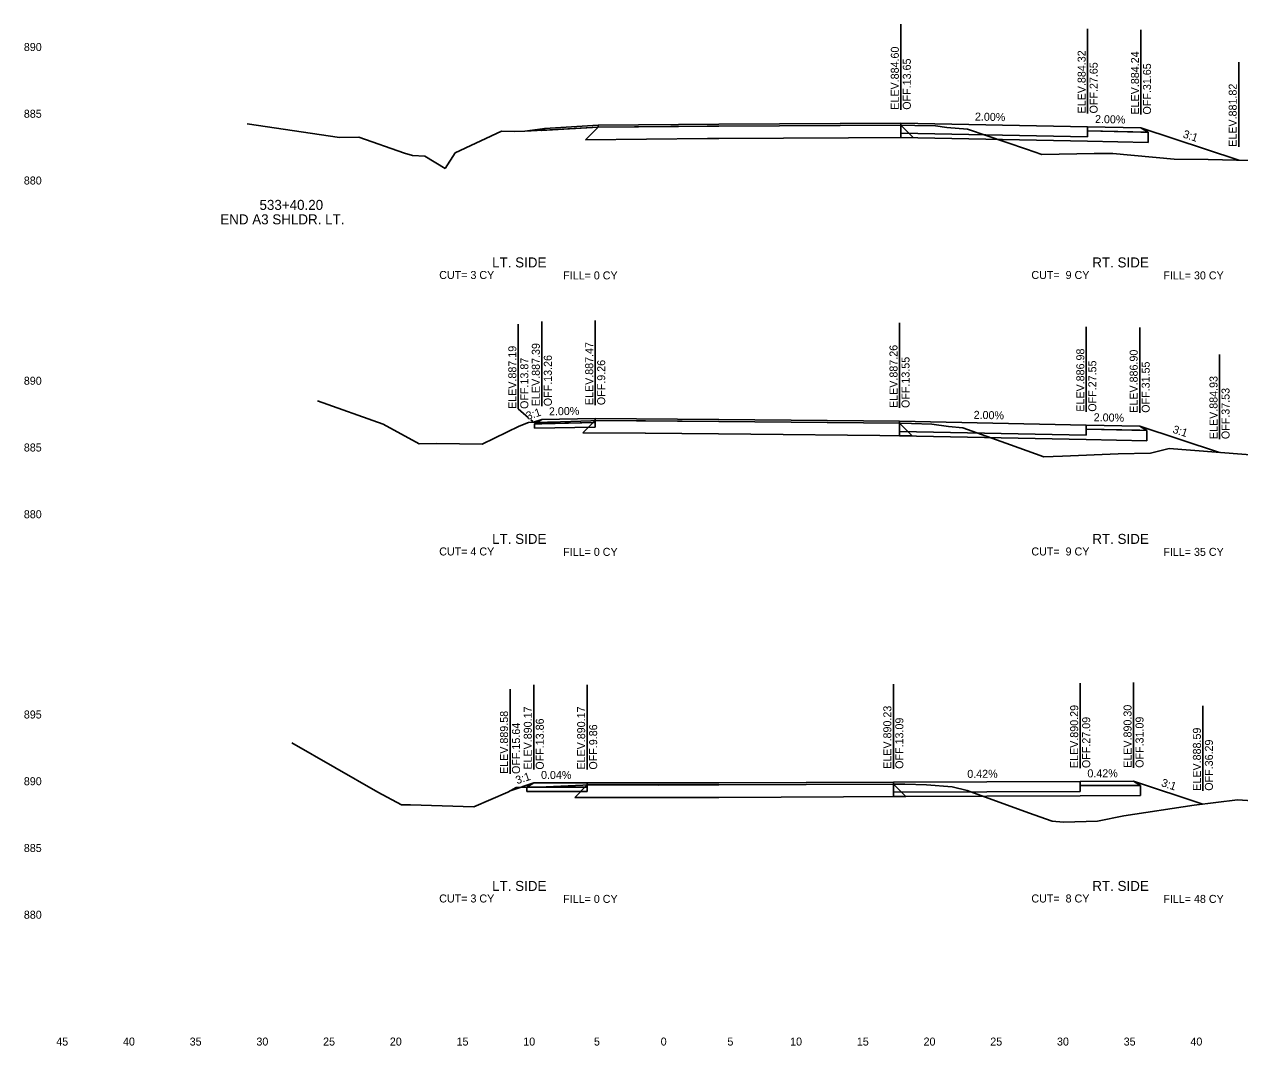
# Model space of a CAD drawing. Extents: x -4 to 359, y 0 to 1436.
# Drawn here: x -3.9 to 87.2, y 600.5 to 677 of the extents above; entities that cross this region are included whole.
import ezdxf

# ---------------------------------------------------------------- set-up
doc = ezdxf.new("R2010")
doc.units = 0
for name, color, linetype in [('XS-Existing subsurface-pavement', 7, 'Continuous'), ('XS-Existing surface-ground', 7, 'Continuous'), ('XS-Proposed Finish Grade', 7, 'Continuous'), ('XS-Proposed subsurface-aggregate layer 1', 7, 'Continuous'), ('XS-Proposed surface-ground', 7, 'Continuous'), ('XS-Proposed surface-pavement', 7, 'Continuous'), ('XS-Proposed surface-shoulder', 7, 'Continuous'), ('XS-Text-ditch slope', 7, 'Continuous'), ('XS-Text-earthwork labels', 7, 'Continuous'), ('XS-Text-elevation', 7, 'Continuous'), ('XS-Text-offset label', 7, 'Continuous'), ('XS-Text-pavement elevation', 7, 'Continuous'), ('XS-Text-pavement slope', 7, 'Continuous'), ('XS-Text-profile report', 7, 'Continuous'), ('XS-Text-shoulder elevation', 7, 'Continuous'), ('XS-Text-shoulder slope', 7, 'Continuous'), ('XS-Text-tie elevation', 7, 'Continuous'), ('XS-Text-tie offset', 7, 'Continuous')]:
    doc.layers.add(name, color=color, linetype=linetype)

msp = doc.modelspace()

# ---------------------------------------------------------------- linework, layer by layer
at = {"layer": 'XS-Existing subsurface-pavement'}
for p, q in [((39.087, 669.279), (38.14, 668.333)), ((61.778, 669.438), (62.711, 668.506)), ((38.14, 668.333), (47.284, 668.421)), ((47.28, 668.421), (48.135, 668.426)), ((48.135, 668.426), (62.711, 668.506)), ((38.873, 647.302), (37.948, 646.377)), ((61.68, 647.097), (62.627, 646.15)), ((37.948, 646.377), (42.631, 646.353)), ((42.626, 646.353), (48.121, 646.297)), ((48.121, 646.297), (62.627, 646.15)), ((38.27, 620.007), (37.335, 619.072)), ((61.217, 620.065), (62.151, 619.132)), ((37.335, 619.072), (43.636, 619.055)), ((43.642, 619.055), (48.134, 619.073)), ((48.134, 619.073), (62.151, 619.132))]:
    msp.add_line(p, q, dxfattribs=at)
at = {"layer": 'XS-Existing surface-ground'}
for p, q in [((12.8, 669.521), (19.7, 668.51)), ((28.377, 667.355), (31.846, 668.982)), ((31.846, 668.982), (32.804, 668.962)), ((32.804, 668.962), (33.597, 668.977)), ((33.597, 668.977), (35.475, 669.075)), ((35.475, 669.075), (39.087, 669.279)), ((39.087, 669.279), (47.275, 669.359)), ((47.275, 669.359), (48.13, 669.363)), ((48.13, 669.363), (61.778, 669.438)), ((61.778, 669.438), (62.819, 669.412)), ((62.819, 669.412), (64.373, 669.383)), ((64.373, 669.383), (65.217, 669.254)), ((65.217, 669.254), (66.774, 669.134)), ((66.774, 669.134), (71.194, 667.624)), ((19.7, 668.51), (21.147, 668.532)), ((21.147, 668.532), (24.578, 667.342)), ((24.578, 667.342), (25.175, 667.153)), ((25.175, 667.153), (26.095, 667.115)), ((26.095, 667.115), (27.635, 666.177)), ((27.635, 666.177), (28.377, 667.355)), ((71.194, 667.624), (72.349, 667.219)), ((72.349, 667.219), (76.263, 667.297)), ((76.263, 667.297), (77.679, 667.317)), ((77.679, 667.317), (82.253, 666.889)), ((82.253, 666.889), (84.816, 666.868)), ((84.816, 666.868), (88.02, 666.783)), ((18.065, 648.788), (22.992, 647.042)), ((22.992, 647.042), (25.681, 645.548)), ((30.394, 645.541), (33.187, 646.872)), ((33.187, 646.872), (33.886, 647.167)), ((33.886, 647.167), (35.303, 647.187)), ((35.303, 647.187), (35.512, 647.182)), ((35.512, 647.182), (38.539, 647.29)), ((38.539, 647.29), (38.873, 647.309)), ((38.873, 647.309), (42.636, 647.29)), ((42.636, 647.29), (48.13, 647.235)), ((48.13, 647.235), (61.68, 647.097)), ((61.68, 647.097), (62.589, 647.073)), ((62.589, 647.073), (64.108, 647.036)), ((64.108, 647.036), (65.347, 646.845)), ((65.347, 646.845), (66.422, 646.759)), ((66.422, 646.759), (69.996, 645.492)), ((25.681, 645.548), (26.999, 645.576)), ((26.999, 645.576), (30.394, 645.541)), ((69.996, 645.492), (72.5, 644.585)), ((80.498, 644.868), (81.884, 645.206)), ((81.884, 645.206), (100.006, 643.781)), ((72.5, 644.585), (73.897, 644.625)), ((73.897, 644.625), (78.072, 644.801)), ((78.072, 644.801), (80.498, 644.868)), ((16.137, 623.15), (22.581, 619.452)), ((22.581, 619.452), (24.357, 618.507)), ((29.783, 618.354), (32.329, 619.471)), ((32.329, 619.471), (32.944, 619.825)), ((32.944, 619.825), (34.502, 619.831)), ((34.502, 619.831), (34.66, 619.833)), ((34.66, 619.833), (37.951, 619.995)), ((37.951, 619.995), (38.27, 620.007)), ((38.27, 620.007), (43.638, 619.992)), ((43.638, 619.992), (48.13, 620.011)), ((48.13, 620.011), (61.217, 620.065)), ((61.217, 620.065), (62.086, 620.057)), ((62.086, 620.057), (63.713, 620.014)), ((63.713, 620.014), (65.633, 619.859)), ((65.633, 619.859), (66.749, 619.591)), ((66.749, 619.591), (71.354, 617.924)), ((24.357, 618.507), (25.038, 618.527)), ((25.038, 618.527), (29.783, 618.354)), ((83.759, 618.486), (87.015, 618.901)), ((87.015, 618.901), (89.541, 618.729)), ((71.354, 617.924), (73.109, 617.302)), ((76.519, 617.295), (78.502, 617.68)), ((78.502, 617.68), (83.759, 618.486)), ((73.109, 617.302), (73.977, 617.221)), ((73.977, 617.221), (76.519, 617.295))]:
    msp.add_line(p, q, dxfattribs=at)
at = {"layer": 'XS-Proposed Finish Grade'}
for points in [[(39.087, 669.425), (48.13, 669.509), (61.778, 669.584)], [(61.778, 669.584), (75.778, 669.304)], [(75.778, 669.304), (79.778, 669.224)], [(38.873, 647.455), (34.873, 647.375)], [(38.873, 647.455), (48.13, 647.38), (61.68, 647.243)], [(61.68, 647.243), (75.68, 646.963)], [(75.68, 646.963), (79.68, 646.883)], [(38.27, 620.153), (34.27, 620.151)], [(38.27, 620.153), (48.13, 620.157), (61.217, 620.211)], [(61.217, 620.211), (75.219, 620.269)], [(75.219, 620.269), (79.219, 620.286)]]:
    msp.add_lwpolyline(points, dxfattribs=at)
at = {"layer": 'XS-Proposed subsurface-aggregate layer 1'}
for points in [[(61.778, 668.834), (75.778, 668.554)], [(61.778, 668.501), (61.778, 668.834)], [(75.778, 668.554), (75.778, 668.991)], [(75.778, 668.991), (80.317, 668.901)], [(80.317, 668.901), (80.317, 668.13)], [(80.317, 668.13), (75.778, 668.221), (61.778, 668.501)], [(38.873, 647.143), (34.334, 647.052)], [(34.334, 647.052), (34.334, 646.719)], [(34.334, 646.719), (38.873, 646.809)], [(38.873, 646.809), (38.873, 647.143)], [(61.68, 646.493), (75.68, 646.213)], [(61.68, 646.16), (61.68, 646.493)], [(80.219, 645.789), (75.68, 645.88), (61.68, 646.16)], [(75.68, 646.213), (75.68, 646.651)], [(75.68, 646.651), (80.219, 646.56)], [(80.219, 646.56), (80.219, 645.789)], [(38.27, 619.84), (33.749, 619.838)], [(33.749, 619.838), (33.749, 619.505)], [(33.749, 619.505), (38.27, 619.507)], [(38.27, 619.507), (38.27, 619.84)], [(61.217, 619.461), (75.219, 619.519)], [(61.217, 619.128), (61.217, 619.461)], [(75.219, 619.957), (79.736, 619.975)], [(75.219, 619.519), (75.219, 619.957)], [(79.736, 619.975), (79.736, 619.205)], [(79.736, 619.205), (75.219, 619.186), (61.217, 619.128)]]:
    msp.add_lwpolyline(points, dxfattribs=at)
at = {"layer": 'XS-Proposed surface-ground'}
for points in [[(35.087, 669.179), (33.597, 668.977)], [(79.778, 669.224), (87.102, 666.807)], [(34.873, 647.375), (34.258, 647.172)], [(79.68, 646.883), (85.663, 644.909)], [(34.27, 620.151), (32.488, 619.563)], [(79.219, 620.286), (84.418, 618.57)]]:
    msp.add_lwpolyline(points, dxfattribs=at)
at = {"layer": 'XS-Proposed surface-pavement'}
for points in [[(61.778, 669.584), (48.13, 669.509), (39.087, 669.425)], [(61.778, 669.584), (75.778, 669.304)], [(61.778, 668.834), (61.778, 669.584)], [(61.778, 669.438), (61.778, 669.584)], [(39.087, 669.279), (48.13, 669.363), (61.778, 669.438)], [(39.087, 669.425), (39.087, 669.279)], [(75.778, 668.554), (61.778, 668.834)], [(75.778, 669.304), (75.778, 668.554)], [(38.873, 647.455), (38.873, 647.309)], [(61.68, 647.243), (48.13, 647.38), (38.873, 647.455)], [(38.873, 647.309), (48.13, 647.235), (61.68, 647.097)], [(61.68, 647.243), (75.68, 646.963)], [(61.68, 646.493), (61.68, 647.243)], [(61.68, 647.097), (61.68, 647.243)], [(75.68, 646.963), (75.68, 646.213)], [(75.68, 646.213), (61.68, 646.493)], [(61.217, 620.211), (48.13, 620.157), (38.27, 620.153)], [(38.27, 620.153), (38.27, 620.007)], [(38.27, 620.007), (48.13, 620.011), (61.217, 620.065)], [(61.217, 620.211), (75.219, 620.269)], [(61.217, 619.461), (61.217, 620.211)], [(61.217, 620.065), (61.217, 620.211)], [(75.219, 619.519), (61.217, 619.461)], [(75.219, 620.269), (75.219, 619.519)]]:
    msp.add_lwpolyline(points, dxfattribs=at)
at = {"layer": 'XS-Proposed surface-shoulder'}
for p, q in [((39.096, 669.28), (34.816, 669.016)), ((35.087, 669.179), (34.816, 669.016)), ((39.087, 669.425), (35.087, 669.179))]:
    msp.add_line(p, q, dxfattribs=at)
for points in [[(75.778, 669.304), (79.778, 669.224), (80.317, 668.901)], [(75.778, 668.991), (75.778, 669.304)], [(80.317, 668.901), (79.778, 668.911), (75.778, 668.991)], [(38.873, 647.455), (34.873, 647.375), (34.334, 647.052)], [(34.334, 647.052), (34.873, 647.063), (38.873, 647.143)], [(38.873, 647.143), (38.873, 647.455)], [(75.68, 646.963), (79.68, 646.883), (80.219, 646.56)], [(75.68, 646.651), (75.68, 646.963)], [(80.219, 646.56), (79.68, 646.571), (75.68, 646.651)], [(38.27, 620.153), (34.27, 620.151), (33.749, 619.838)], [(33.749, 619.838), (34.27, 619.838), (38.27, 619.84)], [(38.27, 619.84), (38.27, 620.153)], [(75.219, 620.269), (79.219, 620.286), (79.736, 619.975)], [(75.219, 619.957), (75.219, 620.269)], [(79.736, 619.975), (79.219, 619.973), (75.219, 619.957)]]:
    msp.add_lwpolyline(points, dxfattribs=at)
at = {"layer": 'XS-Text-tie offset'}
for p, q in [((61.778, 670.584), (61.778, 676.982)), ((75.778, 670.304), (75.778, 676.654)), ((79.778, 670.224), (79.778, 676.574)), ((87.102, 667.807), (87.102, 674.157)), ((33.11, 648.172), (33.11, 654.522)), ((34.873, 648.375), (34.873, 654.725)), ((38.873, 648.455), (38.873, 654.805)), ((61.68, 648.243), (61.68, 654.621)), ((75.68, 647.963), (75.68, 654.313)), ((79.68, 647.883), (79.68, 654.281)), ((85.663, 645.909), (85.663, 652.259)), ((33.11, 648.172), (33.886, 647.496)), ((34.054, 647.35), (34.193, 647.229)), ((75.219, 621.269), (75.219, 627.619)), ((79.219, 621.286), (79.219, 627.684)), ((32.488, 620.827), (32.488, 627.177)), ((34.27, 621.151), (34.27, 627.501)), ((38.27, 621.153), (38.27, 627.503)), ((61.217, 621.211), (61.217, 627.561)), ((84.418, 619.57), (84.418, 625.92))]:
    msp.add_line(p, q, dxfattribs=at)

# ---------------------------------------------------------------- texts
at = {"layer": 'XS-Text-ditch slope'}
for rotation, p in [(341.73711, (82.87, 668.52)), (18.26289, (33.806, 647.339)), (341.73711, (82.101, 646.4)), (18.26289, (33.02, 620.054)), (341.73711, (81.248, 619.932))]:
    msp.add_text('3:1', height=0.6, rotation=rotation, dxfattribs=at).set_placement(p)
at = {"layer": 'XS-Text-earthwork labels'}
for s, height, p in [('533+40.20', 0.75, (13.713, 663.08)), ('END A3 SHLDR. LT.', 0.75, (10.774, 661.998)), ('LT. SIDE', 0.75, (31.148, 658.771)), ('RT. SIDE', 0.75, (76.127, 658.771)), (' CUT= 3 CY           ', 0.6, (26.96, 657.906)), ('FILL= 0 CY           ', 0.6, (36.472, 657.874)), (' CUT=  9 CY           ', 0.6, (71.341, 657.906)), ('FILL= 30 CY           ', 0.6, (81.452, 657.874)), ('LT. SIDE', 0.75, (31.148, 638.06)), ('RT. SIDE', 0.75, (76.127, 638.06)), (' CUT= 4 CY           ', 0.6, (26.96, 637.195)), ('FILL= 0 CY           ', 0.6, (36.472, 637.163)), (' CUT=  9 CY           ', 0.6, (71.341, 637.195)), ('FILL= 35 CY           ', 0.6, (81.452, 637.163)), ('LT. SIDE', 0.75, (31.148, 612.065)), ('RT. SIDE', 0.75, (76.127, 612.065)), (' CUT= 3 CY           ', 0.6, (26.96, 611.2)), ('FILL= 0 CY           ', 0.6, (36.472, 611.168)), (' CUT=  8 CY           ', 0.6, (71.341, 611.2)), ('FILL= 48 CY           ', 0.6, (81.452, 611.168))]:
    msp.add_text(s, height=height, dxfattribs=at).set_placement(p)
at = {"layer": 'XS-Text-elevation'}
for s, p in [('           890           ', (-6.4, 674.982)), ('           885           ', (-6.4, 669.982)), ('           880           ', (-6.4, 664.982)), ('           890           ', (-6.4, 649.982)), ('           885           ', (-6.4, 644.982)), ('           880           ', (-6.4, 639.982)), ('           895           ', (-6.4, 624.982)), ('           890           ', (-6.4, 619.982)), ('           885           ', (-6.4, 614.982)), ('           880           ', (-6.4, 609.982))]:
    msp.add_text(s, height=0.6, dxfattribs=at).set_placement(p)
at = {"layer": 'XS-Text-offset label'}
for s, p in [('           45           ', (-3.97, 600.482)), ('           40           ', (1.03, 600.482)), ('           35           ', (6.03, 600.482)), ('           30           ', (11.03, 600.482)), ('           25           ', (16.03, 600.482)), ('           20           ', (21.03, 600.482)), ('           15           ', (26.03, 600.482)), ('           10           ', (31.03, 600.482)), ('           5           ', (36.33, 600.482)), ('           0           ', (41.33, 600.482)), ('           0           ', (41.33, 600.482)), ('           5           ', (46.33, 600.482)), ('           10           ', (51.03, 600.482)), ('           15           ', (56.03, 600.482)), ('           20           ', (61.03, 600.482)), ('           25           ', (66.03, 600.482)), ('           30           ', (71.03, 600.482)), ('           35           ', (76.03, 600.482)), ('           40           ', (81.03, 600.482))]:
    msp.add_text(s, height=0.6, dxfattribs=at).set_placement(p)
at = {"layer": 'XS-Text-pavement elevation'}
for s, p in [('ELEV.884.60', (61.628, 670.584)), ('ELEV.884.32', (75.628, 670.304)), ('OFF.13.65', (62.528, 670.584)), ('OFF.27.65', (76.528, 670.304)), ('ELEV.887.47', (38.723, 648.455)), ('ELEV.887.39', (34.723, 648.375)), ('ELEV.887.26', (61.53, 648.243)), ('ELEV.886.98', (75.53, 647.963)), ('OFF.13.26', (35.623, 648.375)), ('OFF.9.26', (39.623, 648.455)), ('OFF.13.55', (62.43, 648.243)), ('OFF.27.55', (76.43, 647.963)), ('ELEV.890.17', (34.12, 621.151)), ('ELEV.890.17', (38.12, 621.153)), ('ELEV.890.23', (61.067, 621.211)), ('ELEV.890.29', (75.069, 621.269)), ('OFF.13.86', (35.02, 621.151)), ('OFF.13.09', (61.967, 621.211)), ('OFF.27.09', (75.969, 621.269)), ('OFF.9.86', (39.02, 621.153))]:
    msp.add_text(s, height=0.6, rotation=90, dxfattribs=at).set_placement(p)
at = {"layer": 'XS-Text-pavement slope'}
for s, rotation, p in [('2.00%', 358.85424, (67.328, 669.773)), ('2.00%', 358.85424, (67.23, 647.432)), ('0.42%', 0.23815, (66.761, 620.534))]:
    msp.add_text(s, height=0.6, rotation=rotation, dxfattribs=at).set_placement(p)
at = {"layer": 'XS-Text-profile report'}
for s, p in [('Pvmt_Surf_Asph_T1', (48.116, 669.508)), ('Pvmt_Surf_Asph_T1_R', (61.763, 669.583)), ('Pvmt_Surf_Asph_T2_L', (39.071, 669.424)), ('Pvmt_Surf_Asph_T_L', (39.072, 669.278)), ('Pvmt_Surf_Asph_T', (48.117, 669.363)), ('Pvmt_Surf_Asph_T_R', (61.764, 669.437)), ('Pvmt_Surf_Conc_B_R', (61.764, 668.833)), ('Pvmt_Surf_Conc_T1_R', (75.763, 669.303)), ('Shldr_Surf_Asph_B13', (75.763, 668.991)), ('Shldr_Surf_Asph_T11', (79.763, 669.223)), ('Shldr_Surf_Asph_B11', (79.763, 668.911)), ('Shldr_Surf_Asph_B21', (80.302, 668.9)), ('Agg_Layer_1_B2', (61.767, 668.5)), ('Pvmt_Surf_Conc_B1_R', (75.763, 668.553)), ('Agg_Layer_1_B11', (75.766, 668.22)), ('Agg_Layer_1_B12', (80.305, 668.129)), ('Rt_Agg_Layer_1_B13', (83.258, 668.07)), ('Fill_Slope_2_B1', (87.09, 666.806)), ('Fill_Slope_2_B', (34.246, 647.171)), ('Shldr_Surf_Asph_B2', (34.319, 647.051)), ('Shldr_Surf_Asph_T1', (34.858, 647.374)), ('Shldr_Surf_Asph_B1', (34.858, 647.062)), ('Pvmt_Surf_Asph_T2_L', (38.857, 647.454)), ('Shldr_Surf_Asph_B12', (38.857, 647.142)), ('Pvmt_Surf_Asph_T_L', (38.858, 647.309)), ('Agg_Layer_1_B', (38.862, 646.809)), ('Pvmt_Surf_Asph_T1', (48.116, 647.38)), ('Pvmt_Surf_Asph_T', (48.117, 647.234)), ('Pvmt_Surf_Asph_T1_R', (61.664, 647.242)), ('Pvmt_Surf_Asph_T_R', (61.665, 647.097)), ('Pvmt_Surf_Conc_T1_R', (75.664, 646.962)), ('Shldr_Surf_Asph_T11', (79.665, 646.882)), ('Agg_Layer_1_B1', (34.323, 646.718)), ('Pvmt_Surf_Conc_B_R', (61.665, 646.492)), ('Agg_Layer_1_B2', (61.668, 646.159)), ('Shldr_Surf_Asph_B13', (75.664, 646.65)), ('Pvmt_Surf_Conc_B1_R', (75.664, 646.212)), ('Agg_Layer_1_B11', (75.668, 645.879)), ('Shldr_Surf_Asph_B11', (79.665, 646.57)), ('Shldr_Surf_Asph_B21', (80.203, 646.559)), ('Agg_Layer_1_B12', (80.207, 645.788)), ('Rt_Agg_Layer_1_B13', (83.16, 645.729)), ('Fill_Slope_2_B1', (85.651, 644.908)), ('Fill_Slope_2_B', (33.276, 619.826)), ('Shldr_Surf_Asph_B2', (33.734, 619.837)), ('Agg_Layer_1_B1', (33.738, 619.504)), ('Shldr_Surf_Asph_T1', (34.256, 620.15)), ('Shldr_Surf_Asph_B1', (34.256, 619.838)), ('Pvmt_Surf_Asph_T2_L', (38.255, 620.152)), ('Shldr_Surf_Asph_B12', (38.255, 619.839)), ('Pvmt_Surf_Asph_T_L', (38.256, 620.006)), ('Agg_Layer_1_B', (38.26, 619.506)), ('Pvmt_Surf_Asph_T1', (48.116, 620.156)), ('Pvmt_Surf_Asph_T', (48.117, 620.01)), ('Pvmt_Surf_Asph_T1_R', (61.202, 620.21)), ('Pvmt_Surf_Asph_T_R', (61.202, 620.064)), ('Pvmt_Surf_Conc_B_R', (61.202, 619.46)), ('Shldr_Surf_Asph_B111', (75.203, 619.956)), ('Pvmt_Surf_Conc_T1_R', (75.204, 620.268)), ('Pvmt_Surf_Conc_B1_R', (75.204, 619.518)), ('Shldr_Surf_Asph_T11', (79.204, 620.285)), ('Shldr_Surf_Asph_B11', (79.204, 619.972)), ('Shldr_Surf_Asph_B21', (79.721, 619.975)), ('Agg_Layer_1_B2', (61.206, 619.127)), ('Agg_Layer_1_B11', (75.207, 619.185)), ('Agg_Layer_1_B12', (79.724, 619.204)), ('Rt_Agg_Layer_1_B13', (82.446, 619.215)), ('Fill_Slope_2_B1', (84.406, 618.569))]:
    msp.add_text(s, height=0.00167, dxfattribs=at).set_placement(p)
at = {"layer": 'XS-Text-shoulder elevation'}
for s, p in [('ELEV.884.24', (79.628, 670.224)), ('OFF.31.65', (80.528, 670.224)), ('ELEV.886.90', (79.53, 647.883)), ('OFF.31.55', (80.43, 647.883)), ('ELEV.890.30', (79.069, 621.286)), ('OFF.31.09', (79.969, 621.286))]:
    msp.add_text(s, height=0.6, rotation=90, dxfattribs=at).set_placement(p)
at = {"layer": 'XS-Text-shoulder slope'}
for s, rotation, p in [('2.00%', 358.85424, (76.328, 669.593)), ('2.00%', 1.14577, (35.411, 647.686)), ('2.00%', 358.85424, (76.23, 647.252)), ('0.04%', 0.02347, (34.814, 620.451)), ('0.42%', 0.23815, (75.762, 620.571))]:
    msp.add_text(s, height=0.6, rotation=rotation, dxfattribs=at).set_placement(p)
at = {"layer": 'XS-Text-tie elevation'}
for s, p in [('ELEV.881.82', (86.952, 667.807)), ('ELEV.887.19', (32.96, 648.172)), ('OFF.13.87', (33.86, 648.172)), ('ELEV.884.93', (85.513, 645.909)), ('OFF.37.53', (86.413, 645.909)), ('ELEV.889.58', (32.338, 620.827)), ('OFF.15.64', (33.238, 620.827)), ('ELEV.888.59', (84.268, 619.57)), ('OFF.36.29', (85.168, 619.57))]:
    msp.add_text(s, height=0.6, rotation=90, dxfattribs=at).set_placement(p)

doc.saveas('drawing.dxf')
